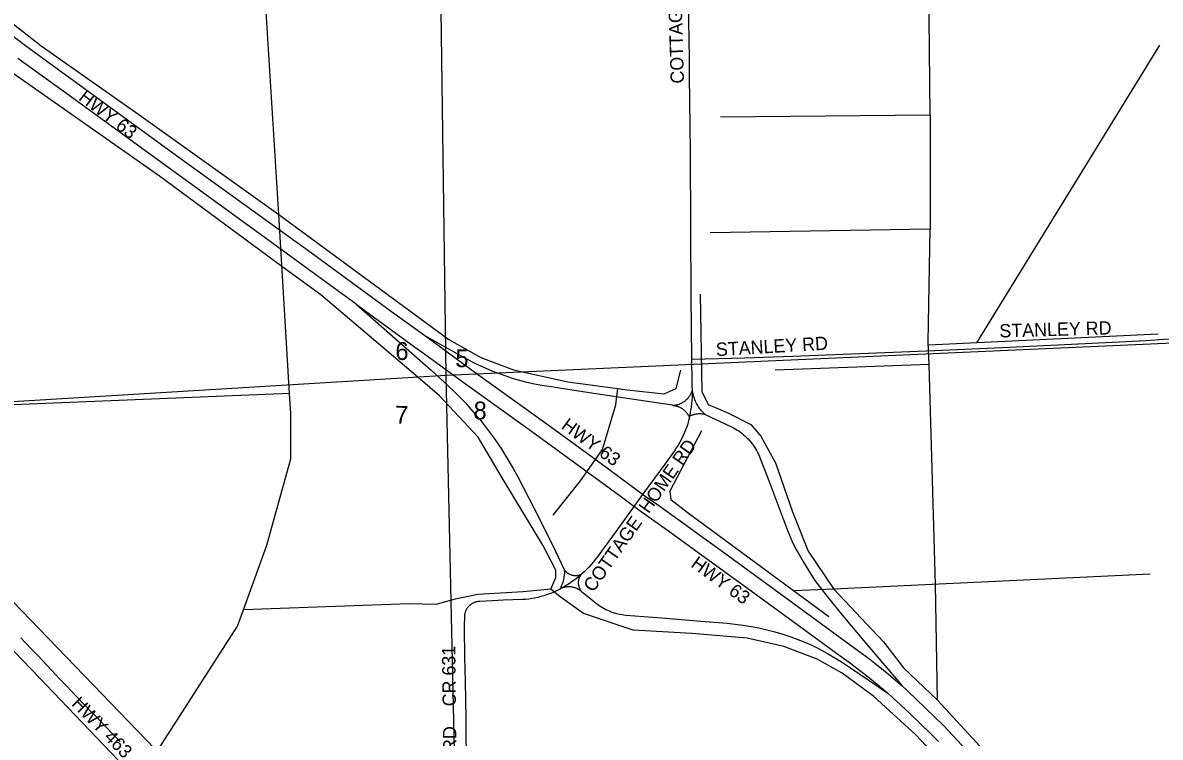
# Model space of a CAD drawing. Extents: x 1670563 to 1761545, y 515755 to 578944.
# Drawn here: x 1728380 to 1734767, y 526521 to 530534 of the extents above; entities that cross this region are included whole.
import ezdxf

# ---------------------------------------------------------------- set-up
doc = ezdxf.new("R2010")
doc.units = 0
for name, color, linetype in [('5_sectionlines', 7, 'Continuous'), ('62_text', 7, 'Continuous'), ('LIMITS', 7, 'Continuous'), ('RR Tracks', 7, 'Continuous'), ('SHP_LINE', 7, 'Continuous'), ('STREETCL', 7, 'Continuous'), ('STRNAMES', 7, 'Continuous')]:
    doc.layers.add(name, color=color, linetype=linetype)

# ---------------------------------------------------------------- blocks, each defined once
blk = doc.blocks.new('CITY_LIMITS02')
at = {"layer": 'LIMITS'}
blk.add_lwpolyline([(1732427.2, 523026.3), (1725619.7, 530087.6)], dxfattribs=at)
blk = doc.blocks.new('RR TRACKS02')
at = {"layer": 'RR Tracks'}
for p, q in [((1728368.3, 527078.9), (1728391.8, 527055.4)), ((1728391.8, 527055.4), (1728434, 527009.7)), ((1728434, 527009.7), (1728463.7, 526979.8)), ((1728463.7, 526979.8), (1728516.3, 526923.7)), ((1728516.3, 526923.7), (1728564.3, 526873.7)), ((1728564.3, 526873.7), (1728587.7, 526847.9)), ((1728587.7, 526847.9), (1728626.6, 526808.3)), ((1728626.6, 526808.3), (1728681.6, 526749.9)), ((1728681.6, 526749.9), (1728722.7, 526707.1)), ((1728722.7, 526707.1), (1728762.7, 526665.9)), ((1728762.7, 526665.9), (1728796.6, 526631.5)), ((1728796.6, 526631.5), (1728811.7, 526615)), ((1728811.7, 526615), (1728879.9, 526544.7)), ((1728879.9, 526544.7), (1728926.7, 526497.2))]:
    blk.add_line(p, q, dxfattribs=at)

msp = doc.modelspace()

# ---------------------------------------------------------------- linework, layer by layer
at = {"layer": '5_sectionlines'}
for points in [[(1730944.5, 517989.2), (1730876.1, 523232.2), (1730757.7, 528552.2), (1730680.7, 534158.4)], [(1742759.9, 529084.4), (1741410.5, 529011.7), (1736058.1, 528787.9), (1730757.7, 528552.2), (1725240.1, 528217.8)]]:
    msp.add_lwpolyline(points, dxfattribs=at)
at = {"layer": 'SHP_LINE'}
for points in [[(1729817, 529457), (1729717, 531076), (1729675, 531352), (1729632, 531519), (1729551, 531727), (1729403, 532037), (1728788, 533308), (1728243, 534397)], [(1729835, 529164), (1729147, 529673), (1728325, 530249), (1728107, 530427), (1727646, 530810), (1727305, 531089), (1726908, 531421), (1726291, 531963), (1725754, 532403), (1724858, 533178), (1724056, 533846), (1723650, 534197)], [(1725583, 532888), (1726970, 531690), (1728131, 530681), (1728483, 530405), (1729031, 530019), (1729817, 529457)], [(1733476, 530017), (1733465, 530927)], [(1733737, 528736), (1734765, 530407)], [(1732298, 530005), (1733476, 530017)], [(1733476, 530017), (1733476, 529374)], [(1729877, 528451), (1728280, 528386), (1728198, 528426), (1728178, 529864)], [(1729877, 528451), (1729817, 529457)], [(1729817, 529457), (1730772, 528754), (1730952, 528653), (1731135, 528584), (1731440, 528517), (1731722, 528479)], [(1733476, 529374), (1732239, 529353)], [(1733464, 528739), (1733476, 529374)], [(1731345, 527353), (1731374, 527418), (1731374, 527459), (1731301, 527599), (1731077, 527969), (1730937, 528206), (1730720, 528439), (1730561, 528575), (1730053, 529005), (1729835, 529164)], [(1732184, 529010), (1732193, 528462), (1732229, 528390), (1732336, 528345), (1732469, 528277), (1732524, 528212), (1732606, 528063), (1732703, 527787), (1732791, 527567), (1732935, 527352)], [(1734755, 528785), (1733465, 528723)], [(1733469, 528615), (1733464, 528739)], [(1733469, 528615), (1732604, 528583)], [(1733505, 527379), (1733469, 528615)], [(1731722, 528479), (1731773, 528472), (1731982, 528450), (1732048, 528479), (1732075, 528582)], [(1731359, 527768), (1731512, 527962), (1731635, 528137), (1731710, 528387), (1731722, 528479)], [(1729619, 527237), (1729750, 527600), (1729885, 528085), (1729885, 528339), (1729877, 528451)], [(1732192, 528241), (1732013, 527903), (1732018, 527857), (1732111, 527786), (1732906, 527199)], [(1734710, 527437), (1732935, 527352)], [(1733517, 526729), (1733505, 527379)], [(1733498, 526093), (1733511, 526411), (1733394, 526534), (1733158, 526749), (1732982, 526881), (1732840, 526959), (1732653, 527031), (1732448, 527078), (1732137, 527104), (1731807, 527122), (1731529, 527216), (1731397, 527309), (1731345, 527353), (1731190, 527337), (1730936, 527322), (1730807, 527296), (1730700, 527267), (1730550, 527270), (1729619, 527237)], [(1732935, 527352), (1732710, 527344)], [(1732935, 527352), (1733213, 527056), (1733325, 526911), (1733517, 526729)], [(1728235, 525608), (1729146, 526459), (1729586, 527145), (1729619, 527237)], [(1733517, 526729), (1733755, 526470), (1734009, 526159), (1734050, 526089), (1734217, 525800), (1734390, 525430), (1734549, 525034), (1734640, 524645), (1734702, 524190), (1734709, 523851), (1734686, 523424), (1734608, 523124), (1734528, 522702)]]:
    msp.add_lwpolyline(points, dxfattribs=at)
at = {"layer": 'STREETCL'}
for points in [[(1732137, 528645.2), (1732136.9, 528648.9), (1732133.6, 528993.6), (1732131.7, 529382.7), (1732129, 529807.9), (1732127.7, 529950.3), (1732124.4, 530233.2), (1732123.1, 530335.5), (1732117.9, 530646)], [(1728237.3, 530523.1), (1728394.2, 530405.1), (1728554, 530289.1), (1729284.7, 529758.4), (1730001.5, 529240.7), (1730450.6, 528911.3), (1730630.5, 528782.7), (1730648.1, 528769.7)], [(1730252, 528953.6), (1729984.3, 529148.8), (1729809.4, 529276.2), (1728982.2, 529875.4), (1728653.2, 530115.7), (1728352.7, 530332.4)], [(1730252, 528953.6), (1730580.1, 528714.4), (1730629.2, 528679), (1730797, 528557.1), (1730871.1, 528502.7), (1731236.8, 528239.2), (1731644.8, 527942.2), (1731709.1, 527895.2), (1731741.5, 527870.7), (1731788.6, 527835.9), (1731840, 527797.3), (1732000.1, 527684.2), (1732076, 527629.2), (1732157.9, 527570.5), (1732491.1, 527328.7), (1732970.5, 526978.8), (1733025.3, 526938.3), (1733056.7, 526915), (1733118.3, 526867.8), (1733178.5, 526818.8), (1733237.2, 526768), (1733358.6, 526656.8), (1733477, 526542.5), (1733522.2, 526496.6)], [(1730252, 528953.6), (1730673.5, 528581.9), (1730739.1, 528523.4), (1730802.8, 528462.9), (1730864.6, 528400.4), (1730907.9, 528351.4), (1730949.7, 528301), (1730989.8, 528249.4), (1731028.3, 528196.5), (1731065.2, 528142.5), (1731100.3, 528087.3), (1731133.7, 528031), (1731158.9, 527984.4), (1731280.6, 527747), (1731368.7, 527569.8), (1731419.4, 527463.9), (1731420.9, 527461.7), (1731422.5, 527459.6), (1731424.1, 527457.5), (1731425.8, 527455.5), (1731427.6, 527453.6), (1731429.5, 527451.7), (1731431.4, 527449.9), (1731433.3, 527448.1), (1731435.4, 527446.4), (1731437.4, 527444.8), (1731439.6, 527443.3), (1731441.8, 527441.8), (1731444, 527440.4), (1731446.3, 527439.1), (1731448.6, 527437.8), (1731451, 527436.7), (1731453.4, 527435.6), (1731455.9, 527434.6), (1731458.3, 527433.7), (1731460.9, 527432.9), (1731463.4, 527432.2), (1731466, 527431.5), (1731468.5, 527431), (1731471.1, 527430.5), (1731473.7, 527430.1), (1731476.4, 527429.8), (1731479, 527429.6), (1731481.6, 527429.5), (1731484.3, 527429.5), (1731486.9, 527429.6), (1731489.6, 527429.7), (1731492.2, 527430), (1731494.8, 527430.3), (1731497.4, 527430.8), (1731500, 527431.3), (1731502.6, 527431.9), (1731505.1, 527432.6), (1731507.6, 527433.4), (1731510.1, 527434.3), (1731512.6, 527435.2), (1731515, 527436.3), (1731517.4, 527437.4), (1731519.7, 527438.6)], [(1732137, 528645.2), (1732434.6, 528651.2), (1732703.5, 528661.3), (1733127.3, 528678.6), (1733500.7, 528693.3), (1733920.9, 528711.7), (1734269.5, 528729.1), (1734688.9, 528749.2), (1734788.2, 528756.6), (1735008.1, 528764.8), (1735569.5, 528786.8), (1735933.9, 528796.9), (1735955.3, 528797.8), (1735975.2, 528797.6), (1735995.2, 528797.9), (1736015.1, 528799), (1736034.9, 528800.8), (1736054.7, 528803.3), (1736074.4, 528806.5), (1736094, 528810.3)], [(1732028.7, 528385.3), (1731824.8, 528415.8), (1731723.9, 528431.7), (1731475.7, 528468.5), (1731336.3, 528490.1), (1731294.3, 528496.6), (1731252.6, 528504.6), (1731211.2, 528513.9), (1731170.1, 528524.6), (1731129.4, 528536.6), (1731089.2, 528550), (1731016.4, 528576.9), (1730928, 528616.1), (1730865.6, 528647.9), (1730648.1, 528769.7)], [(1730648.1, 528769.7), (1730821.1, 528642.1), (1730960.3, 528541.6), (1731085.1, 528451.1), (1731342.4, 528265.3), (1731627.9, 528058.3), (1731887, 527866.5), (1731919.2, 527844.8), (1731957.1, 527819.2), (1732092.3, 527721.3), (1732207.9, 527637.6), (1732301.3, 527570.5), (1732599.8, 527352.7), (1733074.3, 527005.3), (1733136.2, 526958.7), (1733164.6, 526936.4), (1733241.8, 526874.4), (1733317.2, 526810.4)], [(1732140.2, 528472.7), (1732139.6, 528490.2), (1732139.5, 528521.7), (1732137, 528645.2)], [(1732028.7, 528385.3), (1732032.8, 528385.5), (1732036.9, 528385.8), (1732041, 528386.3), (1732045.1, 528386.9), (1732049.1, 528387.6), (1732053.1, 528388.5), (1732057.1, 528389.5), (1732061.1, 528390.7), (1732065, 528392), (1732068.8, 528393.4), (1732072.6, 528395), (1732076.4, 528396.6), (1732080.1, 528398.5), (1732083.7, 528400.4), (1732087.2, 528402.5), (1732090.7, 528404.6), (1732094.1, 528406.9), (1732097.4, 528409.4), (1732100.7, 528411.9), (1732103.8, 528414.5), (1732106.9, 528417.3), (1732109.9, 528420.1), (1732112.7, 528423.1), (1732115.5, 528426.1), (1732118.1, 528429.3), (1732120.7, 528432.5), (1732123.1, 528435.8), (1732125.4, 528439.2), (1732127.6, 528442.7), (1732129.7, 528446.2), (1732131.6, 528449.8), (1732133.5, 528453.5), (1732135.2, 528457.2), (1732136.8, 528461), (1732138.2, 528464.9), (1732139.5, 528468.8), (1732140.7, 528472.7)], [(1732123.4, 528317), (1732127.7, 528336.1), (1732131.5, 528355.4), (1732134.5, 528374.8), (1732137, 528394.3), (1732138.7, 528413.8), (1732139.9, 528433.4), (1732140.4, 528453.1), (1732140.2, 528472.7)], [(1732212.1, 528333.5), (1732206.7, 528338.4), (1732201.5, 528343.5), (1732196.5, 528348.7), (1732191.6, 528354.2), (1732187, 528359.8), (1732182.5, 528365.5), (1732178.2, 528371.4), (1732174.2, 528377.4), (1732170.3, 528383.6), (1732166.7, 528389.9), (1732163.2, 528396.3), (1732160, 528402.9), (1732157, 528409.5), (1732154.3, 528416.2), (1732151.7, 528423.1), (1732149.4, 528430), (1732147.4, 528437), (1732145.5, 528444), (1732144, 528451.1), (1732142.6, 528458.3), (1732141.5, 528465.5), (1732140.7, 528472.7)], [(1732028.7, 528385.3), (1732032.6, 528384.9), (1732036.4, 528384.4), (1732040.2, 528383.8), (1732043.9, 528383.1), (1732047.6, 528382.2), (1732051.4, 528381.2), (1732055, 528380), (1732058.6, 528378.8), (1732062.2, 528377.4), (1732065.7, 528375.9), (1732069.2, 528374.3), (1732072.6, 528372.5), (1732076, 528370.7), (1732079.3, 528368.7), (1732082.5, 528366.6), (1732085.7, 528364.4), (1732088.7, 528362.1), (1732091.7, 528359.7), (1732094.6, 528357.2), (1732097.5, 528354.6), (1732100.2, 528351.9), (1732102.8, 528349.1), (1732105.4, 528346.3), (1732107.8, 528343.3), (1732110.1, 528340.3), (1732112.4, 528337.1), (1732114.5, 528333.9), (1732116.5, 528330.7), (1732118.4, 528327.3), (1732120.2, 528323.9), (1732121.9, 528320.5), (1732123.4, 528317)], [(1732212.1, 528333.5), (1732207.8, 528334.4), (1732203.4, 528335.2), (1732198.9, 528335.9), (1732194.5, 528336.4), (1732190, 528336.7), (1732185.6, 528336.9), (1732181.1, 528337), (1732176.6, 528336.9), (1732172.2, 528336.6), (1732167.7, 528336.2), (1732163.3, 528335.6), (1732158.9, 528334.9), (1732154.5, 528334), (1732150.2, 528333), (1732145.8, 528331.8), (1732141.6, 528330.5), (1732137.4, 528329.1), (1732133.2, 528327.4), (1732129.1, 528325.7), (1732125, 528323.8)], [(1732123.4, 528317), (1732118.8, 528299.4), (1732113.7, 528281.9), (1732108, 528264.6), (1732101.5, 528246.8), (1732094.4, 528229.3), (1732086.6, 528212.1), (1732078.3, 528195.1), (1732069.3, 528178.4), (1732059.8, 528162), (1732049.7, 528146), (1732039.1, 528130.4), (1731984.6, 528055.6), (1731869.6, 527897.7), (1731711.8, 527679.3), (1731649.5, 527594.1), (1731633.7, 527571.8), (1731608.1, 527536.3), (1731596.5, 527520.9), (1731584.5, 527505.8), (1731572, 527491.1), (1731559, 527476.8), (1731545.5, 527462.9), (1731531.7, 527449.5), (1731517.4, 527436.5)], [(1732212.1, 528333.5), (1732360.3, 528264.5), (1732370.6, 528259.2), (1732380.6, 528253.5), (1732390.4, 528247.4), (1732400.1, 528241), (1732409.5, 528234.3), (1732418.6, 528227.3), (1732427.5, 528219.9), (1732436.2, 528212.3), (1732444.5, 528204.3), (1732452.6, 528196.1), (1732460.4, 528187.6), (1732467.9, 528178.8), (1732475.1, 528169.8), (1732482, 528160.5), (1732488.5, 528151), (1732494.7, 528141.2), (1732500.6, 528131.3), (1732506.1, 528121.1), (1732511.2, 528110.8), (1732570.4, 527956.7), (1732650.1, 527747), (1732676.8, 527679), (1732704.7, 527611.5), (1732724.9, 527571), (1732733.2, 527555.8), (1732763.1, 527503.4), (1732794.9, 527452), (1732828.3, 527401.8), (1732896.5, 527311.4), (1732985, 527203), (1733082.9, 527086.1), (1733134.2, 527024.6), (1733317.2, 526810.4)], [(1730300.9, 524942.9), (1728995.1, 526307.8), (1728470.8, 526857.3), (1727464.4, 527903.3)], [(1731419.4, 527463.9), (1731421.2, 527442.8), (1731420.6, 527435.6), (1731419.7, 527428.3), (1731418.7, 527421.1), (1731417.3, 527413.9), (1731415.8, 527406.8), (1731414, 527399.7), (1731412, 527392.7), (1731409.7, 527385.8), (1731407.2, 527378.9), (1731404.5, 527372.2), (1731401.6, 527365.5), (1731398.5, 527358.9), (1731395.1, 527352.4)], [(1731517.4, 527436.5), (1731501.2, 527422.8), (1731484.6, 527409.5), (1731467.5, 527396.9), (1731450, 527384.9), (1731432, 527373.4), (1731413.8, 527362.6), (1731395.1, 527352.4)], [(1731516.1, 527341.7), (1731510.3, 527352), (1731509, 527354.3), (1731507.9, 527356.6), (1731506.8, 527358.9), (1731505.8, 527361.3), (1731504.9, 527363.7), (1731504.1, 527366.1), (1731503.3, 527368.6), (1731502.7, 527371.1), (1731502.1, 527373.6), (1731501.6, 527376.1), (1731501.2, 527378.7), (1731500.9, 527381.2), (1731500.6, 527383.8), (1731500.5, 527386.4), (1731500.5, 527388.9), (1731500.5, 527391.5), (1731500.6, 527394.1), (1731500.8, 527396.7), (1731501.2, 527399.2), (1731501.5, 527401.8), (1731502, 527404.3), (1731502.6, 527406.8), (1731503.2, 527409.3), (1731504, 527411.8), (1731504.8, 527414.2), (1731505.7, 527416.6), (1731506.7, 527419), (1731507.8, 527421.3), (1731508.9, 527423.6), (1731510.1, 527425.9), (1731511.4, 527428.1), (1731512.8, 527430.3), (1731514.3, 527432.4), (1731515.8, 527434.5), (1731517.4, 527436.5)], [(1731395.1, 527352.4), (1731385, 527347.3), (1731369.5, 527339.8), (1731353.7, 527332.9), (1731337.7, 527326.5), (1731321.5, 527320.6), (1731305.1, 527315.3), (1731288.5, 527310.6), (1731271.8, 527306.4), (1731254.9, 527302.8), (1731237.9, 527299.8), (1731220.8, 527297.4), (1731203.7, 527295.5), (1731186.5, 527294.2), (1731076.7, 527290.4), (1731018.3, 527287.7), (1730946.8, 527283.3), (1730943.8, 527283.3), (1730940.8, 527283.1), (1730937.8, 527282.9), (1730934.8, 527282.5), (1730931.8, 527282), (1730928.9, 527281.5), (1730925.9, 527280.8), (1730923, 527280), (1730920.1, 527279.2), (1730917.3, 527278.2), (1730914.5, 527277.1), (1730911.7, 527276), (1730909, 527274.7), (1730906.3, 527273.4), (1730903.7, 527271.9), (1730901.1, 527270.4), (1730898.5, 527268.8), (1730896.1, 527267.1), (1730893.7, 527265.3), (1730891.3, 527263.4), (1730889, 527261.4), (1730886.8, 527259.4), (1730884.7, 527257.3), (1730882.6, 527255.1), (1730880.6, 527252.9), (1730878.7, 527250.5), (1730876.9, 527248.2), (1730875.1, 527245.7), (1730873.5, 527243.2), (1730871.9, 527240.6), (1730870.4, 527238), (1730869, 527235.4), (1730867.7, 527232.7), (1730866.5, 527229.9), (1730865.4, 527227.1), (1730864.4, 527224.3), (1730863.5, 527221.4), (1730862.6, 527218.5), (1730861.9, 527215.6), (1730861.3, 527212.7), (1730860.8, 527209.7), (1730860.4, 527206.7), (1730857.8, 527137.5), (1730861, 526968.7), (1730863.7, 526834.3), (1730867, 526628.7), (1730868.6, 526528.9), (1730871.8, 526339.5)], [(1731516.1, 527341.7), (1731493.7, 527355.4), (1731490.3, 527357), (1731486.8, 527358.4), (1731483.2, 527359.7), (1731479.6, 527360.9), (1731476, 527362), (1731472.3, 527362.9), (1731468.6, 527363.7), (1731464.8, 527364.4), (1731461.1, 527364.9), (1731457.3, 527365.4), (1731453.5, 527365.6), (1731449.7, 527365.8), (1731446, 527365.8), (1731442.2, 527365.7), (1731438.4, 527365.4), (1731434.6, 527365.1), (1731430.8, 527364.5), (1731427.1, 527363.9), (1731423.4, 527363.1), (1731419.7, 527362.2), (1731416.1, 527361.2), (1731412.4, 527360), (1731408.9, 527358.8), (1731405.3, 527357.4), (1731401.9, 527355.8), (1731398.5, 527354.2), (1731395.1, 527352.4)], [(1731516.1, 527341.7), (1731608.1, 527267.2), (1731616.8, 527260.9), (1731625.7, 527255), (1731634.8, 527249.4), (1731644.1, 527244.1), (1731653.6, 527239.1), (1731663.3, 527234.4), (1731673.1, 527230.1), (1731683, 527226.1), (1731693.1, 527222.5), (1731703.3, 527219.2), (1731713.6, 527216.3), (1731724, 527213.7), (1731734.5, 527211.5), (1731745.1, 527209.6), (1731755.7, 527208.2), (1731766.3, 527207), (1731968.5, 527190.8), (1732187.4, 527173), (1732335.1, 527161.1), (1732380, 527156.7), (1732424.7, 527150.9), (1732469.2, 527143.7), (1732513.4, 527135), (1732557.3, 527124.9), (1732602.8, 527112.9), (1732647.9, 527099.6), (1732692.5, 527084.9), (1732732.2, 527070.4), (1732771.2, 527054.6), (1732809.8, 527037.4), (1732847.7, 527018.9), (1732899.2, 526991.5), (1732949.7, 526962.3), (1732977.8, 526944.8), (1733005.5, 526926.5), (1733032.7, 526907.6), (1733231.7, 526772.9)], [(1733317.2, 526810.4), (1733348.6, 526782.6), (1733552.4, 526586), (1733702.8, 526422.5)]]:
    msp.add_lwpolyline(points, dxfattribs=at)

# ---------------------------------------------------------------- block references
for name in ['CITY_LIMITS02', 'RR TRACKS02']:
    msp.add_blockref(name, (0, 0), dxfattribs=at)

# ---------------------------------------------------------------- texts
at = {"layer": '62_text'}
for s, rotation, p in [('6', 358.93377, (1730471.1, 528640.5)), ('5', 358.93373, (1730808, 528600)), ('8', 358.23331, (1730909.3, 528307.1)), ('7', 358.9338, (1730469.5, 528282.7))]:
    msp.add_text(s, height=100, rotation=rotation, dxfattribs=at).set_placement(p)
at = {"layer": 'STRNAMES'}
for s, rotation, p in [('COTTAGE HOME RD    CR631', 91.67767, (1732093.4, 530193.3)), ('HWY 63', 322.42615, (1728688.4, 530103.8)), ('STANLEY RD', 1.61893, (1733865, 528765.8)), ('STANLEY RD', 3.35188, (1732274.2, 528661)), ('HWY 63', 324.03031, (1731398.4, 528258.4)), ('COTTAGE  HOME RD', 54.91143, (1731583.1, 527330.8)), ('HWY 63', 324.03031, (1732126.3, 527482.3)), ('COTTAGE HOME RD    CR 631', 90.72671, (1730826.2, 525597.6)), ('HWY 463', 314.19567, (1728648.8, 526704.5))]:
    msp.add_text(s, height=75, rotation=rotation, dxfattribs=at).set_placement(p)

doc.saveas('drawing.dxf')
